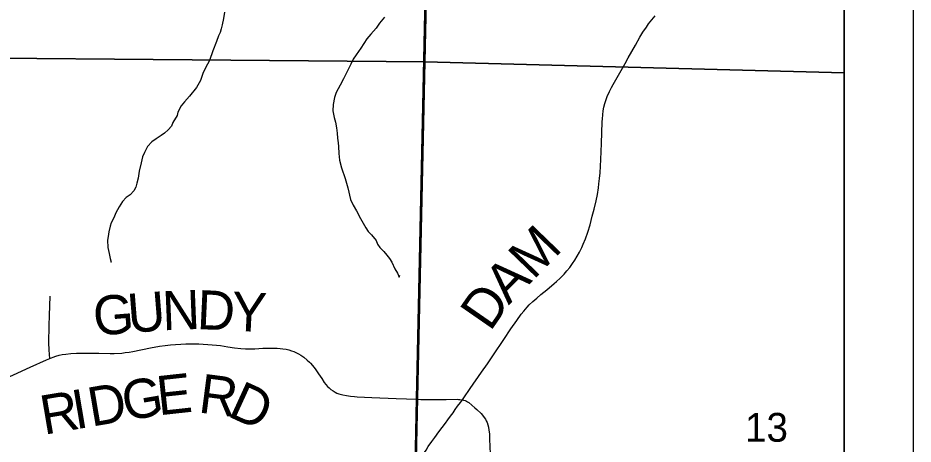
# Model space of a CAD drawing. Extents: x -1.2 to 34, y -8.5 to 22.
# Drawn here: x 7.701 to 9, y 15.11 to 15.729 of the extents above; entities that cross this region are included whole.
import ezdxf

# ---------------------------------------------------------------- set-up
doc = ezdxf.new("R2010")
doc.units = 0
for name, color, linetype in [('GM_X_County_Road', 7, 'Continuous'), ('GM_X_County_Road_Text', 7, 'Continuous'), ('GM_X_Minor_River', 7, 'Continuous'), ('GM_X_Section', 7, 'Continuous'), ('GM_X_Section_Text', 7, 'Continuous'), ('GM_X_Township_Road', 7, 'Continuous'), ('GM_X_Unincorporated_Text', 7, 'Continuous'), ('SH_Cut_Line', 7, 'Continuous'), ('SH_Data', 7, 'Continuous')]:
    doc.layers.add(name, color=color, linetype=linetype)

msp = doc.modelspace()

# ---------------------------------------------------------------- linework, layer by layer
at = {"layer": 'GM_X_County_Road'}
for points in [[(8.3459, 15.1743), (8.3479, 15.1771), (8.3573, 15.1907), (8.3737, 15.2145), (8.3824, 15.2268), (8.391, 15.2396), (8.4059, 15.2621), (8.416, 15.2772), (8.4247, 15.2896), (8.4314, 15.2986), (8.4349, 15.303), (8.4399, 15.3088), (8.4429, 15.3121), (8.448, 15.3171), (8.4537, 15.3221), (8.4599, 15.3272), (8.4682, 15.334), (8.4791, 15.3431), (8.4825, 15.3461), (8.4876, 15.3509), (8.4936, 15.357), (8.4975, 15.3615), (8.5016, 15.3664), (8.5057, 15.3722), (8.5091, 15.3772), (8.5125, 15.3829), (8.5159, 15.3888), (8.5193, 15.3958), (8.5213, 15.4002), (8.5245, 15.4084), (8.5278, 15.418), (8.5311, 15.4287), (8.5344, 15.4409), (8.5371, 15.4511), (8.54, 15.4634), (8.5418, 15.4724), (8.5435, 15.4824), (8.5441, 15.4881), (8.545, 15.496), (8.5458, 15.5039), (8.5468, 15.5232), (8.5477, 15.5465), (8.5488, 15.5781), (8.5491, 15.5823), (8.5495, 15.5884), (8.5502, 15.5942), (8.5514, 15.5996), (8.5526, 15.6046), (8.5542, 15.6093), (8.5562, 15.6151), (8.5592, 15.622), (8.5622, 15.6278), (8.5647, 15.6324), (8.5821, 15.6631), (8.5867, 15.6711), (8.592, 15.6803), (8.5969, 15.6895), (8.6034, 15.7011), (8.608, 15.7086), (8.613, 15.7157), (8.616, 15.7204), (8.6208, 15.7262), (8.6259, 15.7321)], [(7.6699, 15.1994), (7.7186, 15.2218), (7.7421, 15.2322), (7.7472, 15.2344), (7.7519, 15.2363), (7.7557, 15.2377), (7.7606, 15.2391), (7.7652, 15.2401), (7.7706, 15.2408), (7.7775, 15.2416), (7.7858, 15.242), (7.7902, 15.2421), (7.8184, 15.2419), (7.8345, 15.2417), (7.8403, 15.2418), (7.8514, 15.2423), (7.8567, 15.2428), (7.8621, 15.2436), (7.8678, 15.2445), (7.8934, 15.2499), (7.9065, 15.2521), (7.9145, 15.2532), (7.9221, 15.2541), (7.9295, 15.2547), (7.9374, 15.2551), (7.9447, 15.2554), (7.9512, 15.2556), (7.9636, 15.2554), (7.9696, 15.2553), (7.9763, 15.2548), (7.9891, 15.2536), (7.9946, 15.253), (8.0054, 15.2514), (8.0153, 15.25), (8.0245, 15.249), (8.0313, 15.2486), (8.0365, 15.2485), (8.0445, 15.2486), (8.0561, 15.2491), (8.0638, 15.2494), (8.0769, 15.2492), (8.0813, 15.249), (8.0855, 15.2484), (8.0901, 15.2478), (8.0942, 15.2468), (8.0978, 15.2457), (8.1014, 15.2443), (8.1043, 15.243), (8.1078, 15.2412), (8.1116, 15.239), (8.1157, 15.2361), (8.1208, 15.232), (8.124, 15.2291), (8.1254, 15.2277), (8.1308, 15.2211), (8.1333, 15.2177), (8.1372, 15.212), (8.1417, 15.2051), (8.1454, 15.1995), (8.1477, 15.1964), (8.15, 15.1938), (8.1524, 15.1915), (8.155, 15.1893), (8.1582, 15.1872), (8.1611, 15.1855), (8.1638, 15.1842), (8.1666, 15.1832), (8.1722, 15.1817), (8.1778, 15.1805), (8.1834, 15.1796), (8.1894, 15.179), (8.193, 15.1787), (8.2143, 15.1776), (8.25, 15.1761), (8.2797, 15.1751), (8.2854, 15.1749)], [(8.2854, 15.1749), (8.3224, 15.175), (8.3381, 15.1751), (8.34, 15.175), (8.3422, 15.1749), (8.3447, 15.1745), (8.3459, 15.1743), (8.3476, 15.1739), (8.3498, 15.1732), (8.3517, 15.1724), (8.3534, 15.1714), (8.3551, 15.1703), (8.3641, 15.1626), (8.3667, 15.1603), (8.3729, 15.1543), (8.3751, 15.1518), (8.3776, 15.1487), (8.3793, 15.1462), (8.3806, 15.144), (8.3818, 15.1413), (8.383, 15.138), (8.384, 15.1344), (8.3845, 15.1304), (8.385, 15.1251), (8.3854, 15.117), (8.3863, 15.096)], [(8.2835, 15.0857), (8.2877, 15.0927), (8.2931, 15.1013), (8.2961, 15.1063), (8.3013, 15.1137), (8.3057, 15.1197), (8.3118, 15.1279), (8.3164, 15.1339), (8.3213, 15.1405), (8.3247, 15.1451), (8.3287, 15.1506), (8.3323, 15.1554), (8.3356, 15.16), (8.339, 15.1649), (8.3432, 15.1706), (8.3459, 15.1743)]]:
    msp.add_lwpolyline(points, dxfattribs=at)
at = {"layer": 'GM_X_Minor_River'}
for points in [[(8.0007, 15.7375), (7.9993, 15.7283), (7.9972, 15.7192), (7.9957, 15.7134), (7.9943, 15.7081), (7.9921, 15.7031), (7.9892, 15.6947), (7.9837, 15.6813), (7.979, 15.6675), (7.9731, 15.6567), (7.969, 15.6483), (7.9658, 15.6384), (7.9599, 15.628), (7.9498, 15.6153), (7.9424, 15.6072)], [(8.2329, 15.73), (8.2254, 15.7215), (8.2206, 15.7142), (8.2128, 15.7057), (8.2072, 15.6987), (8.1987, 15.6853), (8.1917, 15.6753), (8.1876, 15.6691), (8.1839, 15.6618), (8.1787, 15.6515), (8.1732, 15.6408), (8.1684, 15.6312), (8.1629, 15.6208), (8.1604, 15.6135), (8.1582, 15.6032), (8.158, 15.5941), (8.16, 15.5846), (8.1616, 15.5778), (8.1633, 15.5694), (8.1641, 15.5618), (8.1646, 15.5546), (8.1655, 15.5478), (8.1659, 15.5421), (8.1665, 15.5322), (8.1677, 15.5227), (8.1706, 15.5113), (8.1757, 15.4958), (8.1797, 15.4821), (8.1837, 15.4654), (8.1876, 15.4571), (8.1923, 15.4488), (8.1981, 15.4379), (8.202, 15.4307), (8.2059, 15.4243), (8.209, 15.419), (8.214, 15.4141), (8.2206, 15.4059), (8.2225, 15.4006), (8.226, 15.3957), (8.2318, 15.3897), (8.236, 15.3844), (8.2399, 15.3795), (8.2434, 15.3742), (8.248, 15.3644), (8.2515, 15.3584), (8.2543, 15.3527), (8.2551, 15.3553)], [(7.9424, 15.6072), (7.9379, 15.6014), (7.9328, 15.5922), (7.9317, 15.5872), (7.9258, 15.5772), (7.9236, 15.5719), (7.9187, 15.5665), (7.9135, 15.5618), (7.9086, 15.5583), (7.9015, 15.5533), (7.8951, 15.549), (7.8888, 15.5424), (7.8844, 15.5336), (7.8814, 15.5275), (7.8797, 15.5187), (7.8768, 15.5065), (7.8751, 15.4962), (7.8733, 15.4889), (7.8719, 15.4832), (7.8689, 15.4778), (7.8637, 15.472), (7.8581, 15.4681), (7.8525, 15.4623), (7.8477, 15.4546), (7.8429, 15.4458), (7.84, 15.4385), (7.8363, 15.4316), (7.8348, 15.4266), (7.8327, 15.4182), (7.8316, 15.4114), (7.8306, 15.406), (7.8315, 15.3958), (7.8331, 15.3867), (7.8348, 15.3798), (7.8363, 15.3745), (7.8367, 15.3753)]]:
    msp.add_lwpolyline(points, dxfattribs=at)
at = {"layer": 'GM_X_Section'}
for points in [[(7.2949, 16.6991), (8.3136, 16.6787), (8.2912, 15.6653), (7.2776, 15.674)], [(8.9, 15.6494), (8.9, 16.6645), (8.3136, 16.6787), (8.2912, 15.6653)], [(8.2912, 15.6653), (8.2689, 14.6439), (7.2479, 14.6639), (7.2776, 15.674)], [(8.9, 14.6363), (8.9, 15.6494), (8.2912, 15.6653), (8.2689, 14.6439)]]:
    msp.add_lwpolyline(points, close=True, dxfattribs=at)
at = {"layer": 'GM_X_Township_Road'}
msp.add_lwpolyline([(7.7472, 15.2344), (7.7465, 15.2402), (7.746, 15.2471), (7.7457, 15.2569), (7.7461, 15.2823), (7.7465, 15.2969), (7.7475, 15.325)], dxfattribs=at)
at = {"layer": 'GM_X_Unincorporated_Text'}
for p, q in [((8.2794, 15.1757), (8.2955, 15.9378)), ((8.2772, 15.0742), (8.2794, 15.1757))]:
    msp.add_line(p, q, dxfattribs=at)
msp.add_lwpolyline([(8.2551, 14.1), (8.9, 14.1), (8.9, 17.6758), (8.3326, 17.6871), (8.3265, 17.2224), (8.3029, 16.2873), (8.2955, 15.9378), (8.2794, 15.1757), (8.2772, 15.0742)], close=True, dxfattribs=at)
at = {"layer": 'SH_Cut_Line'}
msp.add_lwpolyline([(2.3586, 14.1), (8.9, 14.1), (8.9, 17.6758), (8.3326, 17.6871), (7.9782, 17.6941), (7.8111, 17.6977), (7.3722, 17.707), (7.1254, 17.7122), (6.7322, 17.7204), (6.6751, 17.7216), (6.665, 17.7216)], dxfattribs=at)
at = {"layer": 'SH_Data'}
for p, q in [((9, 21), (9, 14)), ((9, 21), (9, 14)), ((8.9, 20.9), (8.9, 14.1)), ((8.9, 20.9), (8.9, 14.1))]:
    msp.add_line(p, q, dxfattribs=at)

# ---------------------------------------------------------------- texts
at = {"layer": 'GM_X_County_Road_Text'}
for s, rotation, p in [('M', 46.0022, (8.4489, 15.3475)), ('A', 45.1442, (8.413, 15.3114)), ('U', 4.5546, (7.862, 15.2713)), ('N', 2.2592, (7.9112, 15.2752)), ('D', 357.3872, (7.9599, 15.2772)), ('Y', 357.1392, (8.0098, 15.2749)), ('D', 55.2834, (8.3862, 15.2723)), ('G', 4.6021, (7.8122, 15.2673)), ('G', 9.5815, (7.8569, 15.1435)), ('E', 6.2006, (7.9053, 15.1517)), ('R', 352.6029, (7.9615, 15.1561)), ('I', 9.6304, (7.7846, 15.1313)), ('D', 9.6222, (7.8076, 15.1352)), ('D', 335.4343, (8.0035, 15.1513)), ('R', 9.6311, (7.7386, 15.1234))]:
    msp.add_text(s, height=0.0568, rotation=rotation, dxfattribs=at).set_placement(p)
at = {"layer": 'GM_X_Section_Text'}
msp.add_text('13', height=0.04186, rotation=0, dxfattribs=at).set_placement((8.7561, 15.1134))

doc.saveas('drawing.dxf')
